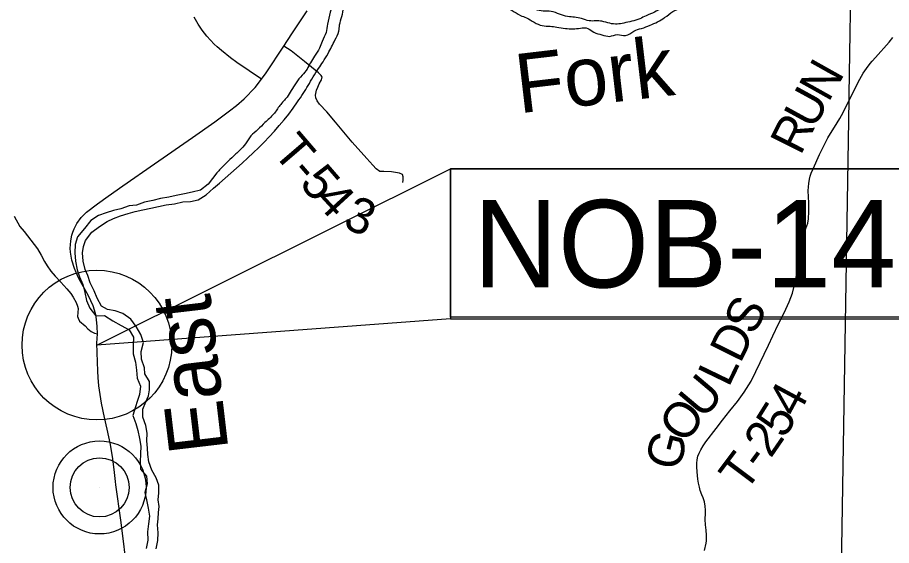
# Model space of a CAD drawing. Extents: x -10 to 158, y 8 to 33.
# Drawn here: x 129.139 to 130.537, y 28.427 to 29.272 of the extents above; entities that cross this region are included whole.
import ezdxf

# ---------------------------------------------------------------- set-up
doc = ezdxf.new("R2010")
doc.units = 0
for name, color, linetype in [('Default', 7, 'Continuous'), ('GM_X_Major_River', 7, 'Continuous'), ('GM_X_Major_River_Text', 7, 'Continuous'), ('GM_X_State_Route', 7, 'Continuous'), ('GM_X_Township_Road', 7, 'Continuous'), ('GM_X_Township_Road_Text', 7, 'Continuous'), ('GM_X_Township_Text', 7, 'Continuous'), ('GM_X_Unincorporated', 7, 'Continuous'), ('GM_X_Unincorporated_Location', 7, 'Continuous'), ('SH_Text', 7, 'Continuous')]:
    doc.layers.add(name, color=color, linetype=linetype)

msp = doc.modelspace()

# ---------------------------------------------------------------- linework, layer by layer
at = {"layer": 'Default'}
msp.add_circle((129.2661, 28.7478), 0.1198, dxfattribs=at)
at = {"layer": 'GM_X_Major_River'}
for points in [[(129.4578, 29.0233), (129.4438, 29.0052), (129.4319, 28.9955), (129.4183, 28.9926), (129.4059, 28.9897), (129.3926, 28.9868), (129.3809, 28.9843), (129.3677, 28.9821), (129.3553, 28.9792), (129.3424, 28.9763), (129.3296, 28.9715), (129.3175, 28.9705), (129.3043, 28.9657), (129.2926, 28.9628), (129.281, 28.9592), (129.2685, 28.9552), (129.2565, 28.947), (129.2462, 28.9342), (129.2351, 28.9211), (129.2311, 28.9085), (129.2306, 28.8956), (129.2317, 28.882), (129.2342, 28.8684), (129.2382, 28.8571), (129.2434, 28.8447), (129.2467, 28.8318), (129.2492, 28.819), (129.2547, 28.8066), (129.2645, 28.7946), (129.2781, 28.7949), (129.2915, 28.7864), (129.3046, 28.7791), (129.3176, 28.7722), (129.3243, 28.7605), (129.3242, 28.7469), (129.324, 28.734), (129.3277, 28.7204), (129.3295, 28.7075), (129.3305, 28.6947), (129.336, 28.6819), (129.3344, 28.6689), (129.3312, 28.6594), (129.3272, 28.6476), (129.3237, 28.6354), (129.3281, 28.6225), (129.3314, 28.6112), (129.3343, 28.5984), (129.3364, 28.5859), (129.3359, 28.5738), (129.335, 28.5612), (129.3356, 28.5495), (129.3453, 28.5379), (129.3463, 28.5258), (129.3428, 28.5121), (129.3453, 28.5), (129.3482, 28.4868), (129.35, 28.4739), (129.3487, 28.4617), (129.347, 28.4492), (129.3477, 28.4355), (129.3449, 28.4222)], [(129.3608, 28.4218), (129.3636, 28.4351), (129.3638, 28.4476), (129.3631, 28.4605), (129.3641, 28.47), (129.3646, 28.4799), (129.3656, 28.4894), (129.3642, 28.5003), (129.3652, 28.5117), (129.3649, 28.5235), (129.3609, 28.5356), (129.3538, 28.5476), (129.349, 28.5611), (129.3473, 28.5728), (129.3471, 28.5827), (129.3461, 28.5948), (129.3466, 28.607), (129.3445, 28.6194), (129.3397, 28.6326), (129.3394, 28.6455), (129.3445, 28.657), (129.3485, 28.6666), (129.3502, 28.6764), (129.3499, 28.6893), (129.3429, 28.7017), (129.3423, 28.7116), (129.3375, 28.7255), (129.3368, 28.7376), (129.3404, 28.7517), (129.3363, 28.7646), (129.3289, 28.7777), (129.3203, 28.7893), (129.3076, 28.7985), (129.2954, 28.8024), (129.2832, 28.8049), (129.2736, 28.81), (129.2666, 28.8228), (129.2614, 28.8344), (129.2551, 28.8476), (129.2514, 28.8589), (129.2475, 28.8687), (129.2438, 28.8822), (129.2428, 28.8951), (129.2448, 28.9054), (129.2477, 28.9149), (129.258, 28.9284), (129.27, 28.9374), (129.2824, 28.9456), (129.2925, 28.9503), (129.3038, 28.9543), (129.3158, 28.9584), (129.3272, 28.9616), (129.3396, 28.9641), (129.3525, 28.9666), (129.377, 28.9721), (129.3902, 28.9738), (129.4035, 28.9767), (129.4156, 28.9773), (129.428, 28.9802), (129.4408, 28.9881), (129.4527, 28.9989)]]:
    msp.add_lwpolyline(points, dxfattribs=at)
for points in [[(130.1791, 29.2914), (130.169, 29.2863), (130.1581, 29.2804), (130.1445, 29.2745), (130.1344, 29.2698), (130.1216, 29.2658), (130.1087, 29.2629), (130.0985, 29.2612), (130.0863, 29.2625), (130.0738, 29.2657), (130.0643, 29.2663), (130.0533, 29.2665), (130.0414, 29.2701), (130.03, 29.2721), (130.019, 29.2735), (130.006, 29.277), (129.9927, 29.2814), (129.9798, 29.2819), (129.9676, 29.2844), (129.9581, 29.288), (129.9328, 29.302), (129.9227, 29.3128), (129.9153, 29.326), (129.9086, 29.3384), (129.9016, 29.3512), (129.8979, 29.3644), (129.8897, 29.3772), (129.8819, 29.3907), (129.8779, 29.4028), (129.8724, 29.4149), (129.8672, 29.4281), (129.8613, 29.4409), (129.8535, 29.4529), (129.8431, 29.466), (129.8337, 29.4788), (129.8217, 29.4915), (129.8117, 29.5004), (129.8013, 29.5131), (129.7886, 29.522), (129.776, 29.5287), (129.763, 29.5334), (129.7507, 29.5385), (129.7366, 29.5428), (129.7267, 29.546), (129.7131, 29.5454), (129.7029, 29.5437), (129.6893, 29.5401), (129.6777, 29.5304), (129.6649, 29.5241), (129.6529, 29.5178), (129.6428, 29.5047), (129.6392, 29.4951), (129.6368, 29.4822), (129.637, 29.4697), (129.6384, 29.4568), (129.639, 29.4442), (129.6396, 29.4313), (129.6402, 29.4188), (129.64, 29.4067), (129.6403, 29.3922), (129.6397, 29.3793), (129.6411, 29.3668), (129.6432, 29.3532), (129.6431, 29.3402), (129.6425, 29.3281), (129.6431, 29.3186), (129.6418, 29.306), (129.6416, 29.2935), (129.6392, 29.2802), (129.635, 29.2611), (129.6325, 29.2478), (129.6263, 29.2336), (129.622, 29.2229), (129.6142, 29.2099), (129.6076, 29.1995), (129.6021, 29.1891), (129.5943, 29.1795), (129.5846, 29.1672), (129.5769, 29.1549), (129.5702, 29.1445), (129.5587, 29.131), (129.5487, 29.1172), (129.5349, 29.104), (129.5233, 29.0924), (129.5125, 29.0824), (129.5036, 29.0697), (129.4947, 29.0597), (129.4816, 29.0473), (129.4701, 29.0361), (129.4578, 29.0233)], [(129.4527, 28.9989), (129.587, 29.1368), (129.5959, 29.1503), (129.604, 29.163), (129.6118, 29.1768), (129.6206, 29.1902), (129.6277, 29.201), (129.6358, 29.214), (129.6468, 29.2355), (129.653, 29.25), (129.6543, 29.2599), (129.6579, 29.2733), (129.6603, 29.2878), (129.6605, 29.298), (129.6607, 29.3075), (129.6594, 29.3174), (129.6599, 29.3291), (129.6605, 29.339), (129.6584, 29.3527), (129.6582, 29.3637), (129.6588, 29.3732), (129.6578, 29.3861), (129.6553, 29.3993), (129.6544, 29.4099), (129.6534, 29.4202), (129.6517, 29.4308), (129.6504, 29.4437), (129.652, 29.4593), (129.6533, 29.4734), (129.6546, 29.4852), (129.6608, 29.4993), (129.6704, 29.5105), (129.6821, 29.5179), (129.6949, 29.5204), (129.7078, 29.5222), (129.7188, 29.5239), (129.7301, 29.5252), (129.7396, 29.5246), (129.7518, 29.5237), (129.7663, 29.519), (129.7793, 29.5109), (129.7924, 29.5005), (129.8028, 29.49), (129.8133, 29.4769), (129.8237, 29.4634), (129.8308, 29.4514), (129.842, 29.4379), (129.8498, 29.4244), (129.8576, 29.412), (129.8655, 29.3961), (129.8725, 29.3849), (129.8761, 29.3751), (129.8767, 29.3644), (129.883, 29.3516), (129.8904, 29.3396), (129.8948, 29.3264), (129.8996, 29.3132), (129.9059, 29.3008), (129.9178, 29.2892), (129.9301, 29.2829), (129.9435, 29.2752), (129.953, 29.2712), (129.9783, 29.2587), (129.9912, 29.2578), (130.0015, 29.2565), (130.0155, 29.2544), (130.0273, 29.2535), (130.0394, 29.2548), (130.0512, 29.2543), (130.0608, 29.2484), (130.0738, 29.244), (130.0863, 29.2416), (130.0988, 29.2445), (130.1117, 29.2428), (130.1249, 29.2499), (130.1373, 29.2543), (130.1509, 29.2594), (130.1742, 29.2716), (130.1873, 29.2813), (130.2012, 29.2873), (130.2125, 29.292)]]:
    msp.add_spline(points, degree=3, dxfattribs=at)
at = {"layer": 'GM_X_State_Route'}
for points in [[(129.4568, 29.1067), (129.463, 29.1112), (129.4782, 29.1223), (129.4895, 29.1312), (129.5018, 29.1416), (129.5191, 29.1599), (129.5293, 29.173), (129.5368, 29.1833), (129.5651, 29.226), (129.578, 29.2457), (129.5895, 29.2632), (129.6023, 29.2825)], [(129.2474, 28.9583), (129.2496, 28.9604), (129.2668, 28.9735), (129.2839, 28.9859), (129.3077, 29.0024), (129.358, 29.0376), (129.4188, 29.0798), (129.4545, 29.105), (129.4568, 29.1067)], [(129.3114, 28.4117), (129.3085, 28.4339), (129.3041, 28.468), (129.2964, 28.524), (129.2959, 28.5298), (129.2943, 28.5442), (129.2915, 28.566), (129.2879, 28.5887), (129.2827, 28.6132), (129.2781, 28.6319), (129.2732, 28.6551), (129.2689, 28.6828), (129.2678, 28.6958), (129.2674, 28.706), (129.266, 28.751), (129.2668, 28.7658), (129.2662, 28.7775), (129.2654, 28.7886), (129.2641, 28.7963), (129.2621, 28.8037), (129.2598, 28.8107), (129.2525, 28.8266), (129.237, 28.8544), (129.2326, 28.8638), (129.2302, 28.8701), (129.2261, 28.8837), (129.2249, 28.8901), (129.224, 28.8965), (129.2235, 28.9029), (129.2237, 28.9081), (129.2243, 28.9144), (129.2259, 28.9238), (129.2273, 28.9285), (129.2297, 28.9339), (129.2341, 28.9423), (129.2409, 28.9518), (129.2474, 28.9583)]]:
    msp.add_lwpolyline(points, dxfattribs=at)
at = {"layer": 'GM_X_Township_Road'}
for points in [[(129.5293, 29.173), (129.4898, 29.1996), (129.4798, 29.2072), (129.4652, 29.2188), (129.4584, 29.2246), (129.4538, 29.2291), (129.4421, 29.2418), (129.4346, 29.2516), (129.4281, 29.2611), (129.4217, 29.2724)], [(130.5063, 29.2018), (130.5117, 29.2079), (130.5331, 29.2325), (130.5393, 29.2398)], [(129.7552, 29.0076), (129.756, 29.0118), (129.7561, 29.0169), (129.7546, 29.0206), (129.7501, 29.023), (129.7374, 29.0247), (129.725, 29.0257), (129.7186, 29.0257), (129.7129, 29.0297), (129.7076, 29.0357), (129.6977, 29.0462), (129.6741, 29.0723), (129.6479, 29.1042), (129.6336, 29.121), (129.6222, 29.133), (129.6183, 29.1384), (129.6163, 29.1435), (129.6157, 29.1476), (129.6174, 29.1553), (129.6194, 29.1602), (129.6214, 29.1658), (129.6251, 29.1719), (129.6261, 29.1764), (129.6245, 29.1792), (129.6207, 29.1831), (129.5982, 29.2014), (129.577, 29.2182), (129.5651, 29.226)], [(130.2377, 28.4192), (130.2404, 28.4308), (130.2409, 28.4349), (130.2412, 28.4436), (130.2405, 28.4516), (130.2393, 28.4602), (130.2389, 28.4687), (130.2393, 28.4787), (130.2397, 28.4836), (130.2389, 28.4903), (130.2377, 28.4972), (130.2356, 28.5033), (130.2336, 28.5084), (130.2311, 28.515), (130.2297, 28.5203), (130.2283, 28.5267), (130.2273, 28.5335), (130.2268, 28.5392), (130.2262, 28.5452), (130.2259, 28.5531), (130.2258, 28.5587), (130.2263, 28.5642), (130.2273, 28.5699), (130.2292, 28.5751), (130.232, 28.5805), (130.236, 28.5866), (130.2401, 28.5931), (130.2564, 28.6143), (130.2666, 28.6277), (130.2784, 28.6427), (130.2907, 28.6578), (130.3014, 28.6725), (130.3124, 28.6902), (130.3198, 28.7056), (130.3401, 28.7477), (130.3473, 28.7628), (130.3565, 28.7819), (130.3655, 28.7992), (130.3735, 28.817), (130.3789, 28.8309), (130.3843, 28.8525), (130.3865, 28.8696), (130.3879, 28.8814), (130.39, 28.896), (130.3925, 28.9085), (130.3936, 28.9123), (130.3986, 28.9298), (130.403, 28.9427), (130.4044, 28.9498), (130.405, 28.9616), (130.405, 28.9754), (130.4044, 28.9847), (130.4039, 28.9947), (130.4041, 29.0007), (130.4048, 29.0065), (130.4057, 29.013), (130.4069, 29.0178), (130.4084, 29.0226), (130.4117, 29.0297), (130.4221, 29.0524), (130.435, 29.0791), (130.45, 29.1032), (130.4543, 29.1102), (130.4596, 29.1198), (130.4694, 29.1396), (130.4864, 29.173), (130.4919, 29.1825), (130.4971, 29.1903), (130.5029, 29.198), (130.5063, 29.2018)], [(129.1337, 28.9541), (129.1429, 28.9373), (129.1495, 28.9294), (129.171, 28.9016), (129.1771, 28.8916), (129.1823, 28.8813), (129.1863, 28.8745), (129.1924, 28.8662), (129.1994, 28.858), (129.2082, 28.8486), (129.218, 28.838), (129.2245, 28.8301), (129.2279, 28.8246), (129.2326, 28.8161), (129.2351, 28.8103), (129.2359, 28.8065), (129.235, 28.7937), (129.2358, 28.7907), (129.2381, 28.7862), (129.2471, 28.7784), (129.2516, 28.774), (129.2567, 28.7695), (129.2623, 28.767), (129.2668, 28.7658)]]:
    msp.add_lwpolyline(points, dxfattribs=at)
at = {"layer": 'GM_X_Township_Text'}
msp.add_lwpolyline([(130.4564, 28.3588), (130.4692, 29.1401), (130.4693, 29.1486), (130.4806, 29.8369), (130.4806, 29.8379), (130.4865, 31.8623), (126.1038, 31.8623), (126.1038, 30.3865)], dxfattribs=at)
at = {"layer": 'GM_X_Unincorporated'}
for radius in [0.0744, 0.0472]:
    msp.add_circle((129.2703, 28.5201), radius, dxfattribs=at)
at = {"layer": 'GM_X_Unincorporated_Location'}
msp.add_line((129.2703, 28.5201), (129.2703, 28.5201), dxfattribs=at)
at = {"layer": 'SH_Text'}
for points in [[(129.2661, 28.7478), (129.8314, 29.0296), (129.8314, 28.7899)], [(131.1693, 29.0299), (129.8314, 29.0299), (129.8314, 28.7899), (131.1693, 28.7899)], [(129.8314, 29.0296), (131.1693, 29.0296), (131.1693, 28.7922), (129.8314, 28.7922)]]:
    msp.add_lwpolyline(points, close=True, dxfattribs=at)

# ---------------------------------------------------------------- texts
at = {"layer": 'GM_X_Major_River_Text'}
for s, rotation, p in [('Fork', 6.7255, (129.9412, 29.1183)), ('East', 96.7272, (129.4767, 28.58))]:
    msp.add_text(s, height=0.09469, rotation=rotation, dxfattribs=at).set_placement(p)
at = {"layer": 'GM_X_Township_Road_Text'}
for s, rotation, p in [('N', 60.7214, (130.4362, 29.1347)), ('U', 61.3264, (130.4123, 29.091)), ('R', 63.2342, (130.3915, 29.0497)), ('T', 310.6534, (129.5455, 29.0557)), ('-', 310.6905, (129.5732, 29.0234)), ('5', 310.8418, (129.5885, 29.0056)), ('4', 312.5472, (129.6126, 28.9777)), ('3', 336.7839, (129.6575, 28.9369)), ('S', 63.7332, (130.3171, 28.7618)), ('D', 63.6956, (130.295, 28.717)), ('L', 64.2399, (130.2765, 28.6788)), ('U', 49.8614, (130.2359, 28.6276)), ('4', 61.68, (130.3858, 28.6298)), ('O', 53.8368, (130.207, 28.588)), ('5', 57.9623, (130.3652, 28.5966)), ('2', 55.4314, (130.3438, 28.5655)), ('G', 75.8242, (130.1972, 28.5447)), ('T', 53.0264, (130.3029, 28.5107)), ('-', 53.6513, (130.3289, 28.5452))]:
    msp.add_text(s, height=0.0568, rotation=rotation, dxfattribs=at).set_placement(p)
at = {"layer": 'SH_Text'}
msp.add_text('NOB-145-0.38', height=0.14, dxfattribs=at).set_placement((129.8684, 28.8399))

doc.saveas('drawing.dxf')
